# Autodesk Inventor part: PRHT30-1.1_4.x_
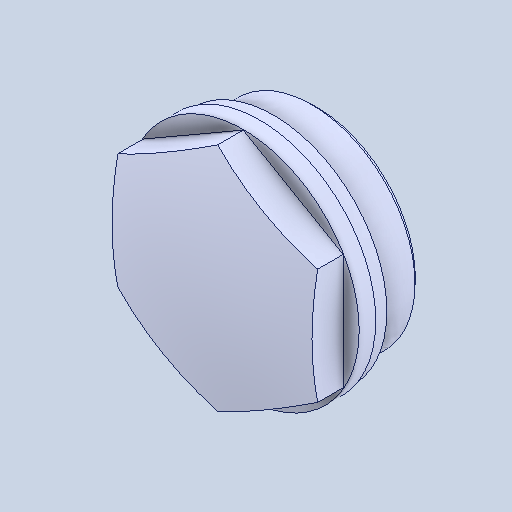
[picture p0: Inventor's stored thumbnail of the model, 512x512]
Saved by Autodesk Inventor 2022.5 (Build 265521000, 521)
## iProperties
Created: 2024-05
Part Number: PRHT30-1.1_4.x_
Material: 一般
Document SubType Name: Modeling
Designer: ImaoCorp
Density: 1 g/cm^3
Appearance: 既定
Author: ImaoCorp
Sending System: SOLIDWORKS 2022-2022290
MC: AMD64
MC_MODEL: Intel64 Family 6 Model 60 Stepping 3, GenuineIntel
OS: Windows_NT
FRU: Parasolid Version 33.1, build 260,  4-25-2022
FORMAT: text
GUISE: transmit
KEY: FILEPRHT30-1.1_4.x_t
DATE: Mon May 20 16:41:19 2024
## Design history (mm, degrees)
feature "Base1"
node "ソリッド1"
